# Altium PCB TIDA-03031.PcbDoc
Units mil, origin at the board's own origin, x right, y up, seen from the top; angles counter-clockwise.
Board outline 3300 x 2000 mil, 2 copper layers (Top Layer, Bottom Layer), stack 61.2 mil thick; 63 components, 29 nets, 150 pads, 94 vias.
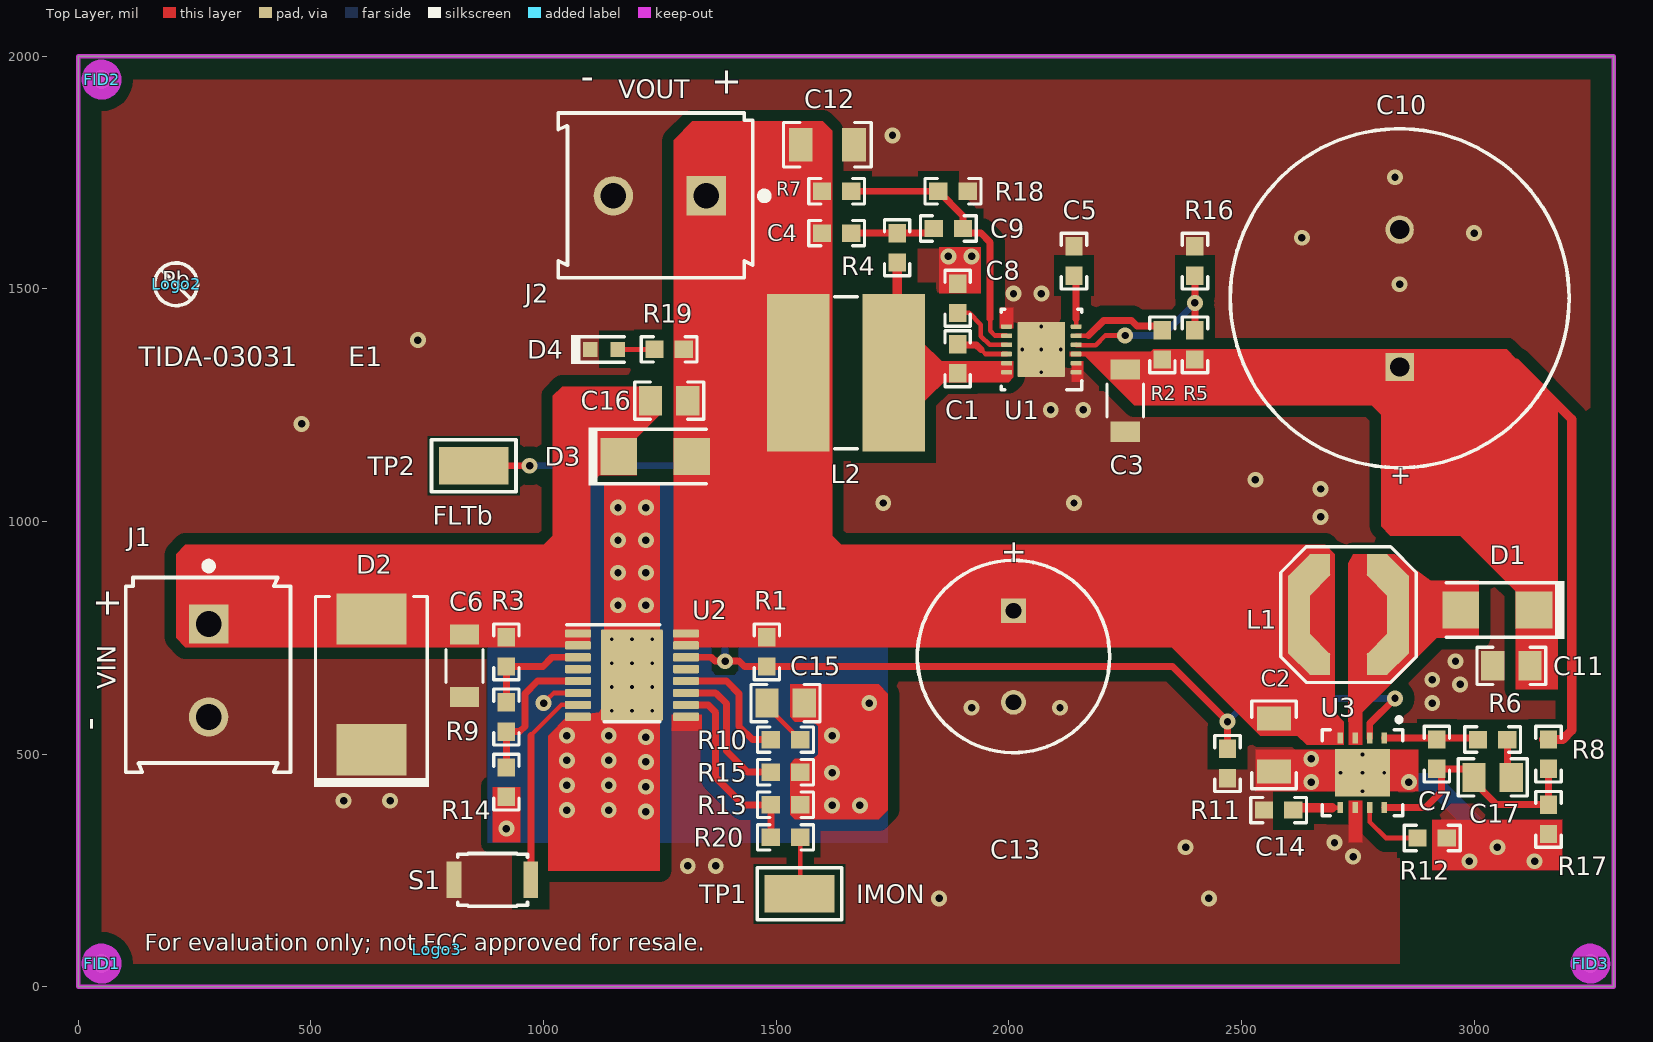
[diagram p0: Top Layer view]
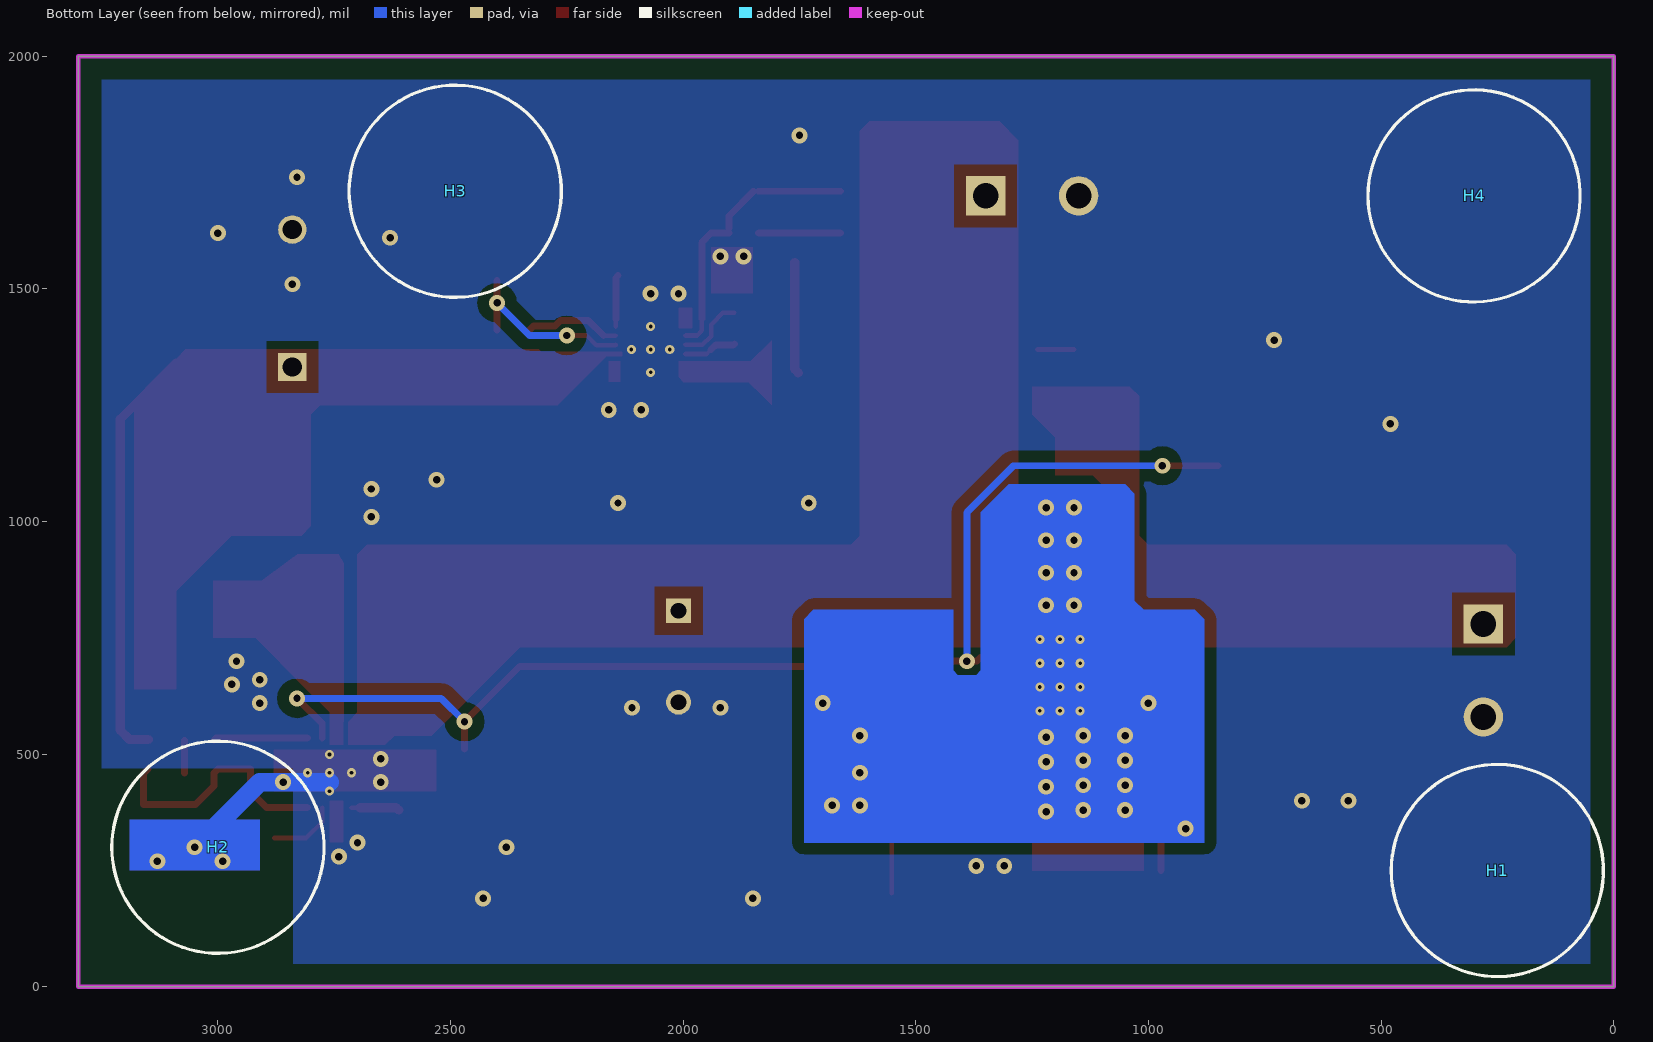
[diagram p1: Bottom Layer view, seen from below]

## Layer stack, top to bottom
Top Solder: solder mask 0.4, Solder Resist, Dk 3.5
Top Layer: signal copper 2.8
Dielectric1: core 55.6, FR-4, Dk 4.8
Bottom Layer: signal copper 2.8
Bottom Solder: solder mask 0.4, Solder Resist, Dk 3.5

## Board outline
0,0 0,2000 3300,2000 3300,0

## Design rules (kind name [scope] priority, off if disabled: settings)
AcuteAngle [All] p1: minimum=4.50000000000000E+0001 checktracksonly=FALSE
AssemblyTestPointUsage [All] p1: valid=2
BoardOutlineClearance BoardOutlineClearance_MountingHoles [OnCopper and InComponentClass('Mounting Holes')] p1: gap=40
BoardOutlineClearance BoardOutlineClearance_Poly [OnCopper and IsPoly] p2: gap=25
BoardOutlineClearance [OnCopper and Not InComponentClass('Logo') and not InComponentClass('FiducialMark') and not InRegion(1000,500,4000,800) and not InPoly] p3: gap=75
Clearance Clearance_Keepouts [((IsTrack Or IsArc) And Not InPoly) And IsFree and IsKeepOut vs ((IsTrack Or IsArc) And Not InPoly) And IsFree and IsKeepOut] p1: gap=0
Clearance Clearance_Poly [InPolygon] p2: gap=25
Clearance [All] p3: gap=7.87
ComponentClearance ComponentClearance_MountingHoles_FiducialMarks [InComponentClass('Mounting Holes') vs InComponentClass('FiducialMark')] p1: gap=50 collisioncheckmode=3 verticalgap=10 showdistances=FALSE
ComponentClearance ComponentClearance_Shunt [InComponentClass('Header') vs InComponentClass('Shunt')] p2: gap=0 collisioncheckmode=3 verticalgap=0 showdistances=FALSE
ComponentClearance ComponentClearance_Logo [InComponentClass('Logo')] p3: gap=50 collisioncheckmode=3 verticalgap=10 showdistances=FALSE
ComponentClearance ComponentClearance_ScrewToNut [(HasFootprint('NY PMS 440 0025 PH')) vs (HasFootprint('Keystone_1902C'))] p4: gap=5 collisioncheckmode=3 verticalgap=10 showdistances=FALSE
ComponentClearance ComponentClearance_MountingHoles [InComponentClass('Mounting Holes')] p5: gap=250 collisioncheckmode=3 verticalgap=100000 showdistances=FALSE
ComponentClearance ComponentClearance_SmallPassives [HasFootprint('0201*') or HasFootprint('0402*') or HasFootprint('0508') or HasFootprint('0603*') or HasFootprint('0612') or HasFootprint('0805*') or HasFootprint('0815*') or HasFootprint('0830*') or HasFootprint('1206*') or HasFootprint('1210*') or HasFootprint('1808*') or HasFootprint('1812*') or HasFootprint('1825*') or HasFootprint('2010*') or HasFootprint('2220*') or HasFootprint('2225*') or HasFootprint('2512*') or HasFootprint('2728*') or HasFootprint('3518*') vs HasFootprint('0201*') or HasFootprint('0402*') or HasFootprint('0508') or HasFootprint('0603*') or HasFootprint('0612') or HasFootprint('0805*') or HasFootprint('0815*') or HasFootprint('0830*') or HasFootprint('1206*') or HasFootprint('1210*') or HasFootprint('1808*') or HasFootprint('1812*') or HasFootprint('1825*') or HasFootprint('2010*') or HasFootprint('2220*') or HasFootprint('2225*') or HasFootprint('2512*') or HasFootprint('2728*') or HasFootprint('3518*')] p6: gap=14.96 collisioncheckmode=3 verticalgap=10 showdistances=FALSE
ComponentClearance ComponentClearance_THtoSMT [IsThruComponent vs IsSMTComponent] p7: gap=40 collisioncheckmode=3 verticalgap=30 showdistances=FALSE
ComponentClearance ComponentClearance_THtoTH [IsThruComponent vs IsThruComponent] p8: gap=30 collisioncheckmode=3 verticalgap=30 showdistances=FALSE
ComponentClearance [All] p9: gap=30 collisioncheckmode=3 verticalgap=10 showdistances=FALSE
DiffPairsRouting [All] p1: maxlimit=100 minlimit=10 mostfreqgap=10 toplayer_minwidth=15 toplayer_maxwidth=15 toplayer_prefwidth=15 bottomlayer_minwidth=15 bottomlayer_maxwidth=15 bottomlayer_prefwidth=15 maxuncoupledlength=1000
FabricationTestPointUsage TestPointUsage [All] p1: valid=2 allowmultiple=FALSE
FabricationTestpoint Testpoint [All] p1: side=3 testpointundercomponent=TRUE minsize=40 maxsize=100 preferedsize=60 minholesize=0 maxholesize=40 preferedholesize=32 testpointgrid=1 allowsidetop=TRUE allowsidebottom=TRUE usegrid=TRUE gridtolerance=0.01
FanoutControl Fanout_LCC [IsLCC] p1: bgadir=Out bgaviamode=Centered fanoutstyle=Auto fanoutdirection=Alternating viagrid=1 // Fanout_LCC (Default Rule)
FanoutControl Fanout_BGA [IsBGA] p2: bgadir=Out bgaviamode=Centered fanoutstyle=Auto fanoutdirection=Alternating viagrid=1 // Fanout_BGA (Default Rule)
FanoutControl Fanout_Default [All] p4: bgadir=Out bgaviamode=Centered fanoutstyle=Auto fanoutdirection=Alternating viagrid=1 // Fanout_Default (Default Rule)
FanoutControl Fanout_Small [(CompPinCount < 5)] p5: bgadir=Out bgaviamode=Centered fanoutstyle=Auto fanoutdirection=OutThenIn viagrid=1 // Fanout_Small (Default Rule)
Height [All] p1: minheight=0 maxheight=1100 prefheight=500
HoleSize [All] p1: absolutevalues=TRUE maxlimit=251 minlimit=7.87 maxpercent=80.000 minpercent=20.000
MinimumAnnularRing MinimumAnnularRing_ThermalPadVias [IsVia and InAnyComponent] p1: minimumring=5.91
MinimumAnnularRing [All] p2: minimumring=8
MinimumSolderMaskSliver MinimumSolderMaskSliver_Logo [InComponentClass('Logo') vs InComponentClass('Logo')] p1: minsoldermaskwidth=0.7
MinimumSolderMaskSliver [All] p2: minsoldermaskwidth=3.94
PlaneConnect [All] p1: planeconnectstyle=Direct reliefexpansion=10 reliefentries=4 reliefconductorwidth=10 reliefairgap=10
PolygonConnect [All] p1: connectstyle=Direct reliefconductorwidth=10 reliefentries=4 polygonreliefangle="90 Angle" airgapwidth=10
RoutingVias ThermalPadVias [IsVia and InAnyComponent] p1: holewidth=7.87 width=19.68 viastyle="Through Hole" minholewidth=7.87 minwidth=19.68 maxholewidth=12.99 maxwidth=23.62
RoutingVias [All] p2: holewidth=16 width=34 viastyle="Through Hole" minholewidth=7.87 minwidth=26 maxholewidth=40 maxwidth=65
SilkToBoardRegionClearance [Not ((IsComment or IsDesignator) And (Hide <> 'False')) and not InRegion(1000,500,4000,800)] p1:
SilkToSilkClearance SilkToSilkClearance_Pb-FreeLogo [(HasFootprint('Pb-Free_Overlay_Medium') OR HasFootprint('Pb-Free_Overlay_Small')) vs (HasFootprint('Pb-Free_Overlay_Medium') OR HasFootprint('Pb-Free_Overlay_Small'))] p1: silktosilkclearance=0
SilkToSilkClearance [All] p2: silktosilkclearance=4
SilkToSolderMaskClearance SilkToComponentPadClearance [IsPad and InAnycomponent] p1: minsilkscreentomaskgap=5 clearancetoexposedcopper=TRUE
SilkToSolderMaskClearance "Silk to Solder Mask Opening" [All] p2: minsilkscreentomaskgap=4 clearancetoexposedcopper=FALSE
SolderMaskExpansion [All] p1: expansion=1.97
Width [All] p1: maxlimit=100 minlimit=6 preferedwidth=10 checkconnectedcopper=TRUE
14 further rules are at their usual default settings.

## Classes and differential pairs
component class TIDA-03031: C1 C2 C3 C4 C5 C6 C7 C8 C9 C10 C11 C12 C13 C14 C15 C16 C17 D1 D2 D3 D4 J1 J2 L1 L2 R1 R2 R3 R4 R5 R6 R7 R8 R9 R10 R11 R12 R13 R14 R15 R16 R17 R18 R19 R20 S1 TP1 TP2 U1 U2 U3
component class TIDA-03031_Hardware: FID1 FID2 FID3 H1 H2 H3 H4 Logo2 Logo3 ZZ1 ZZ2 ZZ3
component class FiducialMark: FID1 FID2 FID3
component class AssemblyNote: ZZ1 ZZ2 ZZ3

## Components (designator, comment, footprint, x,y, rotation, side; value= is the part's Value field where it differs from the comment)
C1 "GRM188R72A103KA01D" 0603 1890,1350 r90 top
C2 "GRM31MR71H105KA88L" 1206 2570,520 r270 top
C3 "GRM31CR72A105KA01L" 1206_180 2250,1260 r270 top
C4 "GRM188R72A332KA01D" 0603 1630,1620 r0 top
C5 "GRM188R71C223KA01D" 0603 2140,1560 r90 top
C6 "GRM31CR72A105KA01L" 1206_180 830,690 r270 top
C7 "GRM1885C1H470JA01D" 0603 2920,500 r270 top
C8 "GRM188R71C105KA12D" 0603 1890,1480 r270 top
C9 "GRM188R72A104KA35D" 0603 1870,1630 r0 top
C10 "UHE1H122MHD6" HE_1800x2500 2840,1480 r90 top
C11 "GRM21BR72A104KAC4L" 0805_HV 3080,690 r0 top
C12 "GRM31MR71H105KA88L" 1206 1610,1810 r0 top
C13 "UHE1V221MPD6" UHE_1000x1250 2010,710 r270 top
C14 "GRM188R71C105KA12D" 0603 2580,380 r180 top
C15 "GRM219R71C225KE15" 0805_HV 1520,610 r0 top
C16 "GRM21BR72A104KAC4L" 0805_HV 1270,1260 r180 top
C17 "GRM219R71C104KA01D" 0805_HV 3040,450 r0 top
D1 "B160-13-F" SMA 3050,810 r180 top
D2 "SMCJ28CA" SMC 630,650 r90 top
D3 "SMAJ51CA" SMA 1240,1140 r0 top
D4 "LTST-C190GKT" LED_LTST-C190 1130,1370 r180 top
FID1 "Fiducial" Fiducial10-20 50,50 r0 top
FID2 "Fiducial" Fiducial10-20 50,1950 r0 top
FID3 "Fiducial" Fiducial10-20 3250,50 r0 top
H1 "SJ-5303 (CLEAR)" Bumpon_SJ5003Transparent 250,250 r180 bottom
H2 "SJ-5303 (CLEAR)" Bumpon_SJ5003Transparent 3000,300 r180 bottom
H3 "SJ-5303 (CLEAR)" Bumpon_SJ5003Transparent 2490,1710 r180 bottom
H4 "SJ-5303 (CLEAR)" Bumpon_SJ5003Transparent 300,1700 r180 bottom
J1 "VIN" TEC_282841-2 280,680 r270 top
J2 "VOUT" TEC_282841-2 1250,1700 r180 top
L1 "LPS6235-333MLB" LPS6235 2730,800 r0 top
L2 "LPS8045B-333MRB" LPS8045B 1650,1320 r180 top
Logo2 "Pb-Free Symbol" Pb-Free_Overlay_Small 210,1510 r0 top
Logo3 "FCC disclaimer" FCC_disclaimer 770,80 r0 top
R1 "CRCW0603100KFKEA" 0603 1480,720 r90 top
R2 "CRCW0603511KFKEA" 0603 2330,1380 r90 top
R3 "CRCW0603715KFKEA" 0603 920,720 r90 top
R4 "CRCW0603100KFKEA" 0603 1760,1588.5 r270 top
R5 "CRCW0603165KFKEA" 0603 2400,1380 r270 top
R6 "CRCW0603715KFKEA" 0603 3040,531.5 r0 top
R7 "CRCW0603226KFKEA" 0603 1630,1710 r180 top
R8 "CRCW060343K2FKEA" 0603 3160,500 r90 top
R9 "CRCW060320K0FKEA" 0603 920,580 r90 top
R10 "CRCW060310K0FKEA" 0603 1520,531.32 r180 top
R11 "CRCW060340K2FKEA" 0603 2470,480 r90 top
R12 "CRCW060343K2FKEA" 0603 2910,320 r180 top
R13 "CRCW060320K0FKEA" 0603 1520,391.32 r180 top
R14 "CRCW060330K1FKEA" 0603 920,440 r90 top
R15 "CRCW06036K04FKEA" 0603 1520,461.32 r180 top
R16 "CRCW060310K0FKEA" 0603 2400,1560 r270 top
R17 "CRCW06031K15FKEA" 0603 3160,360 r90 top
R18 "CRCW060330K1FKEA" 0603 1880,1710 r180 top
R19 "CRCW060320K0FKEA" 0603 1270,1370 r0 top
R20 "CRCW0603100KFKEA" 0603 1520,321.32 r0 top
S1 "SKRKAEE010" SW_SKRKAEE010 890,230 r0 top
TP1 "IMON" Keystone_5019 1550,200 r180 top
TP2 "FLTb" Keystone_5019 850,1120 r0 top
U1 "LM5160DNTR" DNT0012B 2070,1370 r180 top
U2 "TPS26600PWPR" PWP0016D_N 1190,670 r0 top
U3 "LM5002SD/NOPB" SDC08A 2760,460 r270 top
ZZ1 "These assemblies are ESD sensitive, ESD precautions shall be observed." AssemblyNote 185,3829.11 r0 top
ZZ2 "These assemblies must be clean and free from flux and all contaminants. Use of no clean flux is not acceptable." AssemblyNote 185,3740.56 r0 top
ZZ3 "These assemblies must comply with workmanship standards IPC-A-610 Class 2, unless otherwise specified." AssemblyNote 185,3652 r0 top

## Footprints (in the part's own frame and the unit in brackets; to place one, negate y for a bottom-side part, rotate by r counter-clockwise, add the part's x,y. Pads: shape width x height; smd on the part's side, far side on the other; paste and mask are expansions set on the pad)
0603 [mm] "0603 from SM-752 data"
  rect 1x0.95 smd: 1(-0.8,0) 2(0.8,0)
  silkscreen extent -1.52,-0.69 1.52,0.69, body extent -0.87,-0.47 0.87,0.47, height 1
0805_HV [mil] "0805 with 30mil clearance between pads"
  rect 50x63 smd: 1(-40,0) 2(40,0)
  silkscreen extent -74,-40 74,40, body extent -43,-29 43,29, height 57
1206 [mm] "1206 from SM-752 data"
  rect 1.3x1.85 smd: 1(-1.45,0) 2(1.45,0)
  silkscreen extent -2.4,-1.21 2.4,1.21, body extent -1.7,-0.9 1.7,0.9, height 1.35
1206_180 [mm] "1206_180"
  rect 1.1x1.6 smd: 1(-1.7,0) 2(1.7,0)
  silkscreen extent -0.9,-1 0.9,1, body extent -1.75,-0.95 1.75,0.95, height 1.8
AssemblyNote [mil] "Assembly Note"
Bumpon_SJ5003Transparent [mil] "3M Hemispherical Bumpon transparent"
  round 1 on Mech4: 0(0,0)
  silkscreen extent -228,-228 228,228, body extent -219,-218 219,218, height 197
DNT0012B [mm] "SON, 12-Leads, Body 4x4mm, Pitch 0.5mm"
  rrect40% 0.6x0.25 smd: 1(-1.9,1.25) 2(-1.9,0.75) 3(-1.9,0.25) 4(-1.9,-0.25) 5(-1.9,-0.75) 6(-1.9,-1.25) 7(1.9,-1.25) 8(1.9,-0.75) 9(1.9,-0.25) 10(1.9,0.25) 11(1.9,0.75) 12(1.9,1.25)
  rrect4% 2.6x3 smd paste-1.3: 13(0,0)
  silkscreen extent -2.2,-2.2 2.2,2.2, body extent -2,-2 2,2, height 0.81
FCC_disclaimer [mil]
Fiducial10-20 [mm]
  round 1 smd mask+0.5: 1(0,0)
  Top Layer keep-out circle w1.178: c0,0 r0.5
HE_1800x2500 [mm] "TH, 2-Leads, Dia 18mm, Pin Spacing 7.5mm"
  rect 1.55x1.55 hole 1.05: 1(-3.75,0)
  round 1.55 hole 1.05: 2(3.75,0)
  silkscreen extent -9.25,-9.25 9.25,9.25, body extent -9.25,-9.25 9.26,9.25, height 27.01
Keystone_5019 [mm] "Test Point, Miniature, SMT"
  rect 3.8x2.03 smd: 1(0,0)
  silkscreen extent -2.31,-1.42 2.31,1.42, body extent -1.9,-1.02 1.9,1.02, height 2.29
LED_LTST-C190 [mm] "Lite-On"
  rect 0.8x0.8 smd: 1(-0.75,0) 2(0.75,0)
  silkscreen extent -1.1,-0.8 1.8,0.8, body extent -0.85,-0.45 0.85,0.45, height 0.9
LPS6235 [mm] "Coilcraft recommended land pattern.  Document 587-2, rev 10/17/08"
  rect 1.2x4.25 smd: 1(-2.7,0) 2(2.7,0)
  rect 1.68x1.6 smd rot 135: 1(-2.126,-2.151) 2(2.126,2.151)
  rect 1.68x1.6 smd rot 45: 1(-2.126,2.151) 2(2.126,-2.151)
  rect 1.125x1.2 smd: 1(-1.562,-2.7) 1(-1.562,2.7) 2(1.562,-2.7) 2(1.562,2.7)
  silkscreen extent -3.7,-3.7 3.7,3.7, body extent -3.1,-3.1 3.1,3.1, height 3.52
LPS8045B [mm] "COILCRAFT"
  rect 3.4x8.61 smd: 1(-2.605,0) 2(2.605,0)
  silkscreen extent -0.6,-4.15 0.6,4.15, body extent -4.04,-4.04 4.04,4.04, height 4.7
Pb-Free_Overlay_Small [mil]
  silkscreen extent -46,-46 46,46
PWP0016D_N [mm] "TSOP, 16-Leads, Body 5x4.4mm, Pitch 0.65mm, Exposed Pad, IPC Medium Density"
  rrect22% 1.4x0.45 smd: 1(-2.95,2.275) 2(-2.95,1.625) 3(-2.95,0.975) 4(-2.95,0.325) 5(-2.95,-0.325) 6(-2.95,-0.975) 7(-2.95,-1.625) 8(-2.95,-2.275) 9(2.95,-2.275) 10(2.95,-1.625) 11(2.95,-0.975) 12(2.95,-0.325) 13(2.95,0.325) 14(2.95,0.975) 15(2.95,1.625) 16(2.95,2.275)
  rrect6% 3.4x5 smd paste-2 mask-2: 17(0,0)
  rrect4% 2.48x3.4 on Top Solder: 17(0,0)
  rrect4% 2.48x3.4 on Top Paste: 17(0,0)
  silkscreen extent -3.55,-2.55 1.5,2.75, body extent -3.21,-2.5 3.21,2.5, height 1
SDC08A [mm] "SON, 8-Leads, Body 4x4mm, Pitch 0.8mm, NSC Recommended"
  rect 0.6x0.3 smd paste-0.15 mask+0.051: 1(-1.9,1.2) 2(-1.9,0.4) 3(-1.9,-0.4) 4(-1.9,-1.2) 5(1.9,-1.2) 6(1.9,-0.4) 7(1.9,0.4) 8(1.9,1.2)
  rect 2.6x3 smd paste-1.5 mask+0.051: 9(0,0)
  silkscreen extent -3.02,-2.2 2.35,2.2, body extent -2.05,-2.05 2.05,2.05, height 0.8
SMA [mm] "Molded Diode, 2-Leads, Body 4.3x2.6mm, IPC Medium Density, based on OnSemi component dimensions and land pattern"
  rect 2x2 smd: 1(-2,0) 2(2,0)
  silkscreen extent -3.66,-1.57 2.79,1.57, body extent -2.6,-1.3 2.6,1.3, height 2.42
SMC [mil] "Molded Diode, 2-Leads, Body 6.9x5.8mm, IPC Medium Density, based on OnSemi component dimensions and land patterns"
  rect 110x150 smd: 1(-140.49,0) 2(140.49,0)
  silkscreen extent -221,-124 189,123, body extent -156,-116 156,116, height 91
SW_SKRKAEE010 [mm] "Alps recommended land pattern"
  rect 0.8x2 smd: 1(-2.1,0) 2(2.1,0)
  silkscreen extent -1.9,-1.44 1.92,1.44, body extent -2.4,-1.45 2.4,1.45, height 1.96
TEC_282841-2 [mm] "TE Connectivity"
  rect 2.15x2.15 hole 1.4: 1(-2.54,0)
  round 2.15 hole 1.4: 2(2.54,0)
  silkscreen extent -5.9,-4.52 5.55,4.47, body extent -5.08,-4.52 5.58,4.48, height 15.2
UHE_1000x1250 [mm] "TH, 2-Leads, Dia 10mm, Pin Spacing 5mm"
  rect 1.35x1.35 hole 0.85: 1(-2.5,0)
  round 1.35 hole 0.85: 2(2.5,0)
  silkscreen extent -5.25,-5.25 5.25,5.25, body extent -5.25,-5.25 5.26,5.25, height 14.01

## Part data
C1: "CAP, CERM, 0.01 µF, 100 V, +/- 10%, X7R, 0603"
C2 C12: "CAP, CERM, 1 µF, 50 V, +/- 10%, X7R, 1206"
C3 C6: "CAP, CERM, 1 µF, 100 V, +/- 10%, X7R, 1206"
C4: "CAP, CERM, 3300 pF, 100 V, +/- 10%, X7R, 0603"
C5: "CAP, CERM, 0.022 µF, 16 V, +/- 10%, X7R, 0603"
C7: "CAP, CERM, 47 pF, 50 V, +/- 5%, C0G/NP0, 0603"
C8 C14: "CAP, CERM, 1 µF, 16 V, +/- 10%, X7R, 0603"
C9: "CAP, CERM, 0.1 µF, 100 V, +/- 10%, X7R, 0603"
C10: "CAP, AL, 1200 µF, 50 V, +/- 20%, TH"
C11 C16: "CAP, CERM, 0.1 µF, 100 V, +/- 10%, X7R, 0805"
C13: "CAP, AL, 220 µF, 35 V, +/- 20%, TH"
C15: "CAP, CERM, 2.2 µF, 16 V, +/- 10%, X7R, 0805"
C17: "CAP, CERM, 0.1 µF, 16 V, +/- 10%, X7R, 0805"
D1: "Diode, Schottky, 60 V, 1 A, SMA"
D2: "Diode, TVS, Bi, 28 V, 45.4 Vc, SMC"
D3: "Diode, TVS, Bi, 51 V, 400 W, SMA"
D4: "LED, Green, SMD"
FID1 FID2 FID3: "Fiducial mark.  There is nothing to buy or mount."
H1 H2 H3 H4: "Bumpon, Hemisphere, 0.44 X 0.20, Clear"
J1 J2: library part 282841-2, "Terminal Block, 2x1, 5.08mm, TH"
L1: "Inductor, Shielded Drum Core, Ferrite, 33 µH, 1.3 A, 0.18 ohm, SMD"
L2: "Inductor, Shielded, Ferrite, 33 µH, 1.2 A, 0.121 ohm, SMD"
Logo2: library part Pb-Free
Logo3: library part FCC_disclaimer, "FCC_disclaimer"
R1 R4 R20: "RES, 100 k, 1%, 0.1 W, 0603"
R2: "RES, 511 k, 1%, 0.1 W, 0603"
R3 R6: "RES, 715 k, 1%, 0.1 W, 0603"
R5: "RES, 165 k, 1%, 0.1 W, 0603"
R7: "RES, 226 k, 1%, 0.1 W, 0603"
R8 R12: "RES, 43.2 k, 1%, 0.1 W, 0603"
R9 R13 R19: "RES, 20.0 k, 1%, 0.1 W, 0603"
R10 R16: "RES, 10.0 k, 1%, 0.1 W, 0603"
R11: "RES, 40.2 k, 1%, 0.1 W, 0603"
R14 R18: "RES, 30.1 k, 1%, 0.1 W, 0603"
R15: "RES, 6.04 k, 1%, 0.1 W, 0603"
R17: "RES, 1.15 k, 1%, 0.1 W, 0603"
S1: "Switch, Push Button, SMD"
TP1 TP2: library part 5019, "Test Point, Miniature, SMT"
U1: "Wide Input 65V, 1.5A Synchronous Step-Down DC-DC Converter, DNT0012B"
U2: "4.5V-55V, 0.15A-2A, 150mOhm Industrial eFuse, PWP0016D"
U3: "High Voltage Switch Mode Regulator, 8-pin LLP, Pb-Free"
ZZ1 ZZ2 ZZ3: library part AssemblyNote

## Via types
v1: diameter 34, hole 16, Top Layer to Bottom Layer, 72 vias
v2: diameter 19.68, hole 7.87, Top Layer to Bottom Layer, 16 vias
v3: diameter 19.68, hole 7.87, Top Layer to Bottom Layer, tented both sides, 6 vias

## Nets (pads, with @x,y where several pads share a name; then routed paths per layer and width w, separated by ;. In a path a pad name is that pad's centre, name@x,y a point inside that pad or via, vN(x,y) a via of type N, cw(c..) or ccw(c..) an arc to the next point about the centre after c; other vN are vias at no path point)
GND: C2.2 C3.2 C5.2 C6.2 C8.1 C10.2 C11.1 C12.2 C13.2 C14.2 D2.1 D4.2 J1.2 J2.2 R11.1 R12.1 R16.1 R17.1 R18.1 S1.1 U1.1 U1.2 U1.7 U1.13 U2.9 U3.6 U3.9 | length 348
  Bottom Layer w40: 2760,440 2910,440 v1(3050,300)
  other v1: 1850,190 2430,190 1310,260 1370,260 2990,270 3130,270 2740,280 2380,300 2700,310 570,400 670,400 2650,440 2860,440 2650,490 1920,600 2110,600 2910,610 2970,650 2910,660 2960,700 2670,1010 1730,1040 2140,1040 2670,1070 2530,1090 480,1210 2090,1240 2160,1240 730,1390 2010,1490 2070,1490 2840,1510 1870,1570 1920,1570 2630,1610 3000,1620 2830,1740 1750,1830
  other v2: 2760,420.63 2712.76,460 2760,460 2807.24,460 2760,499.37 2070,1320.79 2028.66,1370 2070,1370 2111.34,1370 2070,1419.21
NetC1_1: C1.1 L2.1 R4.2 U1.11 U1.12 | length 240.1
  Top Layer w20: L2.1 1760,1327.44 R4.2
NetC1_2: C1.2 U1.10 | length 114
  Top Layer w10: 1940,1370 1949.84,1360.16 U1.10
  Top Layer w15: C1.2 1891.5,1380 1930,1380 1940,1370
NetC3_1: C3.1 C10.1 C11.2 D1.1 R2.1 R5.2 R8.2 U1.3 | length 906.5
  Top Layer w20: 3090,1340 3210,1220 3210,551.5 3190,531.5 R8.2@3150,531.5
NetC4_2: C4.2 C9.1 R4.1 | length 177
  Top Layer w15: C4.2 C9.1@1838.5,1620
NetC5_1: C5.1 U1.6 | length 111.3
  Top Layer w10: U1.6 2144.8,1435.2
  Top Layer w15: C5.1 2144.8,1523.7 2144.8,1435.2
NetC7_1: C7.1 R6.1 U3.1 | length 203.2
  Top Layer w15: U3.1 3003.7,534.8 R6.1@3008.5,530
NetC7_2: C7.2 C17.1 R8.1 R17.2 U3.8 | length 545.4
  Top Layer w15: U3.8 2895.2,385.2 2930,420 2930,468.5 3000,468.5 3008.5,460 3008.5,431.5 3048.5,391.5 R17.2 3160,458.5 R8.1@3150,468.5
NetC8_2: C8.2 U1.9 | length 148
  Top Layer w10: C8.2 1914.76,1448.5 1940,1423.27 1940,1398.81 1958.97,1379.84 U1.9
NetC9_2: C9.2 R7.1 R18.2 U1.8 | length 575.3
  Top Layer w10: 1960,1435.97 1960,1410 1970,1400 1994.72,1400 U1.8
  Top Layer w15: R7.1 R18.2@1838.5,1710 ; R18.2 1901.5,1657.01 C9.2 ; C9.2@1901.5,1620 1940,1620 1960,1600 1960,1435.97
NetC14_1: C14.1 U3.5 | length 103.4
  Top Layer w10: 2694.8,385.2 U3.5
  Top Layer w20: C14.1 2616.69,385.2 2694.8,385.2
NetC15_1: C15.1 R10.1 | length 108.3
  Top Layer w10: C15.1 1480,602.82 R10.1
NetC17_2: C17.2 R6.2 | length 70
  Top Layer w15: C17.2@3071.5,460 R6.2@3071.5,530
NetD1_2: D1.2 L1.2 U3.3
NetD4_1: D4.1 R19.1 | length 79
  Top Layer w10: D4.1 R19.1
NetR1_1: R1.1 R11.2 TP2.1 U2.14 U3.2 | length 2669.5
  Top Layer w15: TP2.1 v1(970,1120) ; U2.14 1360,708.39 1368.39,700 v1(1390,700) 1420,700 1431.5,688.5 R1.1 2351.5,688.5 v1(2470,570) R11.2 ; U3.2 2775.75,565.75 v1(2830,620)
  Bottom Layer w15: v1(970,1120) 1290,1120 1390,1020 v1(1390,700) ; v1(2470,570) 2520,620 v1(2830,620)
NetR2_2: R2.2 U1.5 | length 207.5
  Top Layer w10: U1.5 2171.1,1399.53
  Top Layer w15: 2171.1,1399.53 2203.94,1432.37 2263.41,1432.37 2275.83,1419.95 2321.54,1419.95 R2.2
NetR3_1: R3.1 R9.2 U2.3 | length 239.1
  Top Layer w15: R9.2 R3.1 998.5,688.5 1018.39,708.39 U2.3
NetR5_1: R5.1 R16.2 U1.4 | length 400.5
  Top Layer w10: U1.4 2144.8,1379.15 2186.79,1379.15 2207.64,1400 v1(2250,1400)
  Top Layer w15: R5.1 v1(2400,1470) R16.2@2400,1518.5
  Bottom Layer w15: v1(2250,1400) 2330,1400 v1(2400,1470)
NetR9_1: R9.1 R14.2 U2.5 | length 316.9
  Top Layer w15: R14.2 R9.1 948.5,548.5 960,560 960,630 987.2,657.2 U2.5
NetR10_2: R10.2 U2.12 | length 275.5
  Top Layer w15: U2.12 1392.8,657.2 1420,630 1420,560 1448.68,531.32 R10.2
NetR12_2: R12.2 U3.7 | length 147.9
  Top Layer w10: U3.7 2775.75,354.25 2810,320 R12.2
NetR13_2: R13.2 R20.1 U2.10 | length 423.3
  Top Layer w15: U2.10 1353.98,606.02 1370,590 1370,450 1428.68,391.32 R13.2 R20.1
NetR15_2: R15.2 U2.11 | length 312.4
  Top Layer w15: U2.11 1370,631.61 1392.87,608.74 1392.87,507.13 1438.68,461.32 R15.2
NetR20_2: R20.2 TP1.1 | length 121.9
  Top Layer w10: R20.2@1550,319.82 R20.2 TP1.1@1551.5,201.5
NetS1_2: S1.2 U2.7 | length 418.7
  Top Layer w10: 972.68,540.24 1038.46,606.02 U2.7
  Top Layer w15: S1.2@972.68,250 972.68,540.24
RTN: C15.2 R13.1 R14.1 R15.1 U2.6 U2.8 U2.17@1190,670 | length 68.7
  Top Layer w10: v1@1010,620 1021.61,631.61 U2.6
  other v1: 920,340 1220,376.67 1050,380 1140,380 1620,390 1680,390 1220,430 1050,433.33 1140,433.33 1620,460 1220,483.33 1050,486.67 1140,486.67 1220,536.67 1050,540 1140,540 1620,540 1000,610 1700,610 1160,820 1220,820 1160,890 1220,890 1160,960 1220,960 1160,1030 1220,1030
  other v2: 1146.69,644.41 1190,644.41 1233.31,644.41 1146.69,695.59 1190,695.59 1233.31,695.59
  other v3: 1146.69,593.23 1190,593.23 1233.31,593.23 1146.69,746.77 1190,746.77 1233.31,746.77
VIN: C6.1 C16.2 D2.2 D3.1 J1.1 R3.2 U2.1 U2.2
VOUT: C2.1 C4.1 C12.1 C13.1 C16.1 D3.2 J2.1 L1.1 L2.2 R1.2 R7.2 R19.2 U2.15 U2.16 U3.4
pads on no net: FID1.1 FID2.1 FID3.1 H1.0 H2.0 H3.0 H4.0 U2.4 U2.13 U2.17@1190,670

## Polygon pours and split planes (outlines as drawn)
GND on Bottom Layer "BOTTOM_LAYER_GND_P006" (solid, remove dead copper, pour order 6): 50,1950 3250,1950 3250,470 2838.15,470 2838.15,50 50,50
GND on Top Layer "TOP_LAYER_GND_P004" (solid, remove dead copper, pour order 4): 50,50 2840,50 2840,360 3250,360 3250,1950 50,1950

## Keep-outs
Keep-Out Layer:
  the board outline again, w10
  text ".Layer_Name" at 577,-858.49 h60

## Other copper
Top Layer:
  rectangle net GND: 1850,1490 1940,1590
  rectangle net GND: 2530,420 2880,510
  rectangle net GND: 2910,250 3190,360
  rectangle net RTN: 890,310 950,430
  rectangle net NetD1_2: 2730,520 2760,580
  rectangle net NetC3_1: 2130,1355 2320,1366
  rectangle net NetC1_1: 1850,1310 2010,1345
  rectangle net GND: 1275,550 1340,585
  rectangle net GND: 2730,310 2760,400
  rectangle net GND: 2135,1300 2160,1345
  rectangle net GND: 1980,1415 2010,1460
  pour cut-out: 1630,1590 1640,1580 1640,1130 1680,1130 1680,1570 1690,1580 1680,1590
  region net VOUT: 1280,730 2040,730 2350,730 2540,540 2620,540 2640,520 2720,520 2720,570 2700,590 2700,930 2680,950 2040,950 1640,950 1620,970 1620,1840 1600,1860 1480,1860 1320,1860 1280,1820
  region net VIN: 1100,730 230,730 210,750 210,930 230,950 1000,950 1020,970 1020,1270 1040,1290 1250,1290 1250,1230 1200,1180 1200,1100 1120,1100 1100,1080 1100,950 1100,790
  region net NetD1_2: 2730,910 2740.25,930.25 2830,930.25 2907,873 3010,873 3010,750.25 2920.25,750.25 2810,640 2760,590 2760,570 2730,570 2730,600
  region net NetC3_1: 3180,870 3180,1050 3180,1260 3090,1350 3070,1370 2310,1370 2300,1360 2160,1360 2190,1330 2270,1250 2780,1250 2800,1230 2800,1200 2800,990 2820,970 2970,970 3090,850 3090,640 3180,640
  region net NetC1_1: 2010,1340 2010,1310 2000,1300 1860,1300 1830,1270 1810,1250 1810,1390 1860,1340
  region net RTN: 1250,250 1010,250 1010,540 1050,580 1120,590 1130,610 1130,1080 1250,1080
  region net RTN: 1530,650 1530,580 1540,570 1580,570 1590,560 1590,500 1580,490 1540,490 1530,480 1530,370 1540,360 1720,360 1740,380 1740,630 1720,650
  text ".Layer_Name" at 577,-858.49 h60
Bottom Layer:
  region net GND: 3190,360 2910,360 2910,250 3190,250
  region net RTN: 880,310 880,790 900,810 1010,810 1030,830 1030,1060 1050,1080 1300,1080 1360,1020 1360,810 1360,690 1360,680 1370,670 1410,670 1420,680 1420,690 1420,730 1420,810 1720,810 1740,790 1740,310
  text ".Layer_Name" at 577,-858.49 h60

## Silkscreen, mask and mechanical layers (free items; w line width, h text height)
Top Overlay:
  text "-" at 1080,1910 h100
  text "+" at 1360,1900 h100
  text "TIDA-03031      E1" at 130,1320 h72.83
  text "+" at 30,780 h100
  text "-" at 70,550 h100 r90
  text ".Layer_Name" at 577,-858.49 h60
Bottom Overlay:
  text ".Layer_Name" at 577,-858.49 h60
Top Paste:
  text ".Layer_Name" at 577,-858.49 h60
Bottom Paste:
  text ".Layer_Name" at 577,-858.49 h60
Top Solder:
  text ".Layer_Name" at 577,-858.49 h60
  text ".Layer_Name" at 577,-858.49 h60
Bottom Solder:
  text ".Layer_Name" at 577,-858.49 h60
Drill Guide:
  text ".Layer_Name" at 577,-858.49 h60
M1 Board Outline:
  the board outline again, w10
  text ".Layer_Name" at 577,-858.49 h60
M2 Board Dimensions:
  rectangle: 0,-275 125,-150
  rectangle: 125,-400 500,-275
  lines w7: 0,-275 1000,-275 ; 125,-400 125,-150 ; 250,-400 250,-150 ; 500,-400 500,-150 ; 750,-400 750,-150 ; 0,-400 1000,-400 1000,-150 0,-150 0,-400
  text ".Layer_Name" at 577,-858.49 h60
M3 3D STEP Top:
  text ".Layer_Name" at 577,-858.49 h60
M4 3D STEP Bottom:
  text ".Layer_Name" at 577,-858.49 h60
M5 Assembly Top:
  lines w10: -292,-930.17 6308,-930.17 ; -292,-726.83 6310,-726.83 ; -292,-523.5 -292,-1133.5 3713,-1133.5 6310,-1133.5 6310,-523.5 -291.5,-523.5 -291.5,-1133.5 1284,-1133.5 ; 2173,-1133.5 2173,-523.5 ; 3440,-726.83 3440,-523.5 ; 4280,-726.83 4280,-523.5 ; 4902,-1140 4902,-937.17
  text "COMPONENTS MARKED 'DNP' SHOULD NOT BE POPULATED." at 1153.5,-318.5 h60
  text "ASSEMBLY VARIANT:" at 1153,-434 h60
  text ".VariantName" at 2189,-434 h60
  text "PCB VIEWED FROM TOP SIDE" at -228.5,-655.67 h60
  text "BOARD #:" at 2248,-655.67 h60
  text ".PRJ_Number" at 2793.5,-655.67 h60
  text "REV:" at 3638,-655.67 h60
  text ".PCB_Rev" at 3929.5,-655.67 h60
  text "SVN REV:" at 4476,-655.67 h60
  text ".VersionControl_RevNumber" at 4982,-655.67 h60
  text "TID #:" at 2248,-859 h60
  text ".TID" at 2793.5,-859 h60
  text "PLOT NAME =" at -228.5,-1064.34 h60
  text ".plot_File_Name" at 577,-1064.34 h60
  text "GENERATED    :" at 2250,-1064.34 h60
  text ".Print_Date" at 3119.5,-1064.34 h60
  text ".Print_Time" at 3848.5,-1064.34 h60
  text "TEXAS INSTRUMENTS" at 5113,-1064.34 h60
M6 Assembly Bottom:
  lines w10: -292.5,-727.33 6309.5,-727.33 ; -290.5,-930.67 6309.5,-930.67 ; 1115.5,-1140.5 1115.5,-937.67 ; 1737.5,-727.33 1737.5,-524 ; 2577.5,-727.33 2577.5,-524 ; 3844.5,-1134 3844.5,-524 ; 4733.5,-1134 6309,-1134 6309,-524 -292.5,-524 -292.5,-1134 2304.5,-1134 6309.5,-1134 6309.5,-524
  text "COMPONENTS MARKED 'DNP' SHOULD NOT BE POPULATED." at 6102,-318 h60
  text ".VariantName" at 5058,-434 h60
  text "ASSEMBLY VARIANT:" at 6097,-434 h60
  text ".VersionControl_RevNumber" at 1035.5,-656.17 h60
  text "SVN REV:" at 1541.5,-656.17 h60
  text ".PCB_Rev" at 2088,-656.17 h60
  text "REV:" at 2379.5,-656.17 h60
  text ".PRJ_Number" at 3224,-656.17 h60
  text "BOARD #:" at 3769.5,-656.17 h60
  text "PCB VIEWED FROM BOTTOM SIDE" at 6246,-656.17 h60
  text ".TID" at 3224,-859.5 h60
  text "TID #:" at 3769.5,-859.5 h60
  text "TEXAS INSTRUMENTS" at 904.5,-1064.84 h60
  text ".Print_Time" at 2169,-1064.84 h60
  text ".Print_Date" at 2898,-1064.84 h60
  text "GENERATED    :" at 3767.5,-1064.84 h60
  text ".plot_File_Name" at 5440.5,-1064.84 h60
  text "PLOT NAME =" at 6246,-1064.84 h60
M9 Title Sheet:
  drawing of 57 lines, arcs and shapes, not listed
  text "1" at 739.84,8036.5 h70
  text "2" at 3235.5,8036.5 h70
  text "3" at 5724.84,8036.5 h70
  text "4" at 8231.51,8036.5 h70
  text "5" at 10730.5,8036.5 h70
  text "6" at 13235.5,8036.5 h70
  text "A" at -416.5,6893.5 h70
  text "A" at 14383.5,6893.5 h70
  text "B" at -416.5,4513.5 h70
  text "B" at 14383.5,4513.5 h70
  text "C" at -416.5,2138.5 h70
  text "C" at 14383.5,2138.5 h70
  text "PROJECT TITLE:" at 11343.5,277.5 h45
  text ".PRJ_Title" at 11393.5,144.17 h70
  text "DESIGNED FOR:" at 11343.5,-23.5 h45
  text ".PRJ_Customer" at 11393.5,-163.5 h70
  text "D" at -416.5,-231.5 h70
  text "D" at 14383.5,-231.5 h70
  text "FILE NAME:" at 11343.5,-323.5 h45
  text ".PCB_File_Name_No_Path" at 11393.5,-443.5 h70
  text "Texas Instruments (TI) and/or its licensors do not warrant the accuracy or completeness of this specification" at 6374,-605.34 h45
  text "ENGINEER:" at 11343.5,-613.5 h45
  text "LAYOUT BY:" at 12848.5,-613.5 h45
  text "or any information contained therein. TI and/or its licensors do not warrant that this design will meet" at 6329.01,-718 h45
  text ".PRJ_Engineer" at 11393.5,-768.49 h70
  text ".PCB_Layout" at 12899,-768.49 h70
  text "the specifications, will be suitable for your application or fit for any particular purpose, or will operate in" at 6329.01,-830.67 h45
  text ".Layer_Name" at 577,-858.49 h60
  text "ALTIUM DESIGNER VERSION:" at 12848.5,-923.5 h45
  text "an implementation. TI and/or its licensors do not warrant that the design is production worthy. You should" at 6329.01,-943.33 h45
  text "completely validate and test your design implementation to confirm the system functionality for your application." at 6374,-1056 h45
  text ".print_Scale" at 11393.5,-1056.83 h70
  text ".Application_BuildNumber" at 12899,-1056.83 h70
  text "1" at 739.84,-1263.5 h70
  text "2" at 3235.5,-1263.5 h70
  text "3" at 5724.84,-1263.5 h70
  text "4" at 8231.51,-1263.5 h70
  text "5" at 10730.5,-1263.5 h70
  text "6" at 13235.5,-1263.5 h70
M10 Fab Notes:
  drawing of 173 lines, arcs and shapes, not listed
  text "DESIGN INFORMATION" at 12378.02,6201 h60
  text "MIN. TRACK WIDTH:" at 11733.46,6021 h60
  text "8" at 12829.7,6021 h60
  text "MIL" at 12984.46,6021 h60
  text "MIN. CLEARANCE:" at 11733.46,5889 h60
  text "0.2" at 12769.7,5889 h60
  text "mm" at 12984.46,5889 h60
  text "MIN. VIA PAD SIZE:" at 11733.46,5757 h60
  text "24" at 12799.71,5757 h60
  text "MIL" at 12984.46,5757 h60
  text "0.05mm (2MIL)" at 12428.46,5615.29 h60
  text "MINIMUM ANNULAR RING" at 11404.23,5611 h60
  text "EXTERNAL" at 13136.46,5611 h60
  text "PER" at 11604.23,5493 h60
  text "IPC-D-275 CLASS 2 LEVEL C" at 11824.23,5493 h60
  text "MIL, HOLES" at 13312.46,5380.71 h60
  text "+/-" at 12920,5380 h60
  text "+/-" at 13774,5380 h60
  text "REGISTRATION TOLERANCES:" at 11404.23,5375 h60
  text "METAL" at 12604,5375 h60
  text "5" at 13180.2,5375 h60
  text "3" at 14013.2,5375 h60
  text "MIL" at 14129.46,5375 h60
  text "+/-" at 13774,5262 h60
  text "HOLE SIZE TOLERANCE (UNLESS OTHERWISE SPECIFIED):" at 11404.23,5257 h60
  text "3" at 14013.2,5257 h60
  text "MIL" at 14129.46,5257 h60
  text "MATERIAL:" at 11329.46,5047.54 h60
  text "FR-4 High Tg" at 12315.9,4907.21 h60
  text "FR-408" at 11750.46,4898.64 h60
  text "OTHER" at 13238.46,4898.64 h60
  text "X" at 12161,4895 h60
  text "62 MIL (1.6mm) +/-10%" at 12070.56,4735.92 h60
  text "THICKNESS:" at 11404.23,4731.64 h60
  text "X" at 11942.4,4731.64 h60
  text "OTHER" at 13355.46,4731.64 h60
  text "TOLERANCE:" at 11404.23,4573.64 h60
  text "X" at 12243.53,4573.64 h60
  text "ANSI IPC-6012 TYPE 3 CLASS 2" at 12430.48,4573.64 h60
  text "OTHER +/-" at 12430.46,4417.64 h60
  text "BOW & TWIST:" at 11404.23,4260.64 h60
  text "X" at 12243.53,4260.64 h60
  text "ANSI IPC-6012 TYPE 3 CLASS 2" at 12430.48,4260.64 h60
  text "OTHER +/-" at 12430.46,4102.13 h60
  text "DRILLING:" at 11329.46,3963.64 h60
  text "REFERENCE:" at 11404.23,3846.64 h60
  text "X" at 12052.46,3846.64 h60
  text "AS SHOWN" at 12239.46,3846.64 h60
  text "X" at 12953.46,3846.64 h60
  text "NC_DRILL FILES" at 13090.46,3846.64 h60
  text "PTH COPPER THICKNESS:" at 11404.23,3688.64 h60
  text "X" at 12534.46,3688.64 h60
  text "20-30 um" at 12671.46,3688.64 h60
  text "OTHER" at 13388.46,3688.64 h60
  text "BOARD FINISH:" at 11329.46,3529.64 h60
  text "SILKSCREEN:" at 11484.68,3411.64 h60
  text "X" at 12433.46,3411.64 h60
  text "TOP" at 12559.46,3411.64 h60
  text "BOTTOM" at 13070.46,3411.64 h60
  text "SILKSCREEN COLOR:" at 11484.68,3244.64 h60
  text "X" at 12432.42,3244.64 h60
  text "WHITE" at 12559.46,3244.64 h60
  text "OTHER" at 13070.46,3244.64 h60
  text "X" at 12563.42,3085.44 h60
  text "GREEN" at 12690.46,3085.44 h60
  text "OTHER" at 13308.46,3085.44 h60
  text "SOLDER RESIST COLOR:" at 11484.68,3074.64 h60
  text "X" at 12563.42,2915.44 h60
  text "MATTE" at 12690.46,2915.44 h60
  text "SEMI-GLOSS" at 13308,2914.8 h60
  text "IMMERSION GOLD (ENIG)" at 12390.46,2726.92 h60
  text "ENEPIG" at 13728,2723.64 h60
  text "SURFACE FINISH:" at 11329.46,2722.64 h60
  text "X" at 12203.51,2722.64 h60
  text "IMM. TIN/SILVER OR EQUIV" at 11659,2565.64 h60
  text "OTHER" at 13090.46,2565.64 h60
  text "ARRAY/PANEL:" at 11329.46,2386.64 h60
  text "CUT AND TRIM PER M1 BOARD OUTLINE" at 12390.46,2382.35 h60
  text "N.C. ROUTE" at 12390.46,2230.64 h60
  text "X" at 13069.46,2230.64 h60
  text "V. SCORE" at 13256.46,2230.64 h60
  text "CERTIFICATION:" at 11329.46,2093.64 h60
  text "MATERIALS AND WORKMANSHIP FOR ALL PCBS" at 12054.46,2093.64 h60
  text "TO MEET OR EXCEED THE REQUIREMENTS OF:" at 12054.46,1995.64 h60
  text "X" at 11680.96,1859.13 h60
  text "ANSI IPC-A-600F CLASS ->" at 11819.96,1859.13 h60
  text "X" at 13459.02,1859.13 h60
  text "2" at 13577.96,1859.14 h60
  text "1" at 13262.96,1857.64 h60
  text "3" at 13931.96,1857.64 h60
  text "X" at 12495.02,1699.64 h60
  text "RoHS" at 12631.96,1699.64 h60
  text "OTHER" at 13276.36,1699.64 h60
  text "PER ORDER" at 13673.42,1699.64 h60
  text "ALL BOARDS MUST MEET OR EXCEED UL94-V0 REQUIREMENTS." at 11357,1534 h60
  text "PCB MUST BEAR THE UL94V-0 UL REGISTERED MATERIAL ID NUMBER" at 11357,1414 h60
  text "ADDITIONAL REQUIREMENTS:" at 11329.46,1240.64 h60
  text "MICROSECTION:" at 11404.23,1125.64 h60
  text "YES" at 12309.96,1125.64 h60
  text "REQUIRED" at 13171.46,969.49 h60
  text "BARE BOARD ELEC. TEST:" at 11404.23,966.64 h60
  text "NONE" at 12709.96,966.64 h60
  text "X" at 13044.46,966.64 h60
  text "PER ORDER" at 13763.46,966.64 h60
  text ".Layer_Name" at 577,-858.49 h60
M11 Gerber Information:
  lines w10: -292,-930.17 6308,-930.17 ; -292,-726.83 6310,-726.83 ; -292,-523.5 -292,-1133.5 3713,-1133.5 6310,-1133.5 6310,-523.5 -291.5,-523.5 -291.5,-1133.5 1284,-1133.5 ; 2173,-1133.5 2173,-523.5 ; 3440,-726.83 3440,-523.5 ; 4280,-726.83 4280,-523.5 ; 4902,-1140 4902,-937.17
  text "ALL ARTWORK VIEWED FROM TOP SIDE" at -228.5,-655.67 h60
  text "BOARD #:" at 2248,-655.67 h60
  text ".PRJ_Number" at 2793.5,-655.67 h60
  text "REV:" at 3638,-655.67 h60
  text ".PCB_Rev" at 3929.5,-655.67 h60
  text "SVN REV:" at 4476,-655.67 h60
  text ".VersionControl_RevNumber" at 4982,-655.67 h60
  text "LAYER NAME =" at -228.5,-858.49 h60
  text "TID #:" at 2248,-859 h60
  text ".TID" at 2793.5,-859 h60
  text "PLOT NAME =" at -228.5,-1064.34 h60
  text ".plot_File_Name" at 577,-1064.34 h60
  text "GENERATED    :" at 2250,-1064.34 h60
  text ".Print_Date" at 3119.5,-1064.34 h60
  text ".Print_Time" at 3848.5,-1064.34 h60
  text "TEXAS INSTRUMENTS" at 5113,-1064.34 h60
M12 Stackup:
  drawing of 191 lines, arcs and shapes, not listed
  text "Layer" at 9727.5,7707.5 h60
  text "Name" at 10137.41,7707.5 h60
  text "Material" at 11067.16,7707.5 h60
  text "Thickness" at 11926.92,7707.5 h60
  text "Constant" at 12576.76,7707.5 h60
  text "Board Layer Stack" at 13146.62,7707.5 h60
  text "1" at 9727.5,7587.5 h60
  text "Top Overlay" at 10137.41,7587.5 h60
  text "2" at 9727.5,7467.5 h60
  text "Top Solder" at 10137.41,7467.5 h60
  text "Solder Resist" at 11067.16,7467.5 h60
  text "0.40mil" at 11926.92,7467.5 h60
  text "3.5" at 12576.76,7467.5 h60
  text "3" at 9727.5,7347.5 h60
  text "Top Layer" at 10137.41,7347.5 h60
  text "Copper" at 11067.16,7347.5 h60
  text "2.80mil" at 11926.92,7347.5 h60
  text "4" at 9727.5,7227.5 h60
  text "Dielectric1" at 10137.41,7227.5 h60
  text "FR-4" at 11067.16,7227.5 h60
  text "55.60mil" at 11926.92,7227.5 h60
  text "4.8" at 12576.76,7227.5 h60
  text "5" at 9727.5,7107.5 h60
  text "Bottom Layer" at 10137.41,7107.5 h60
  text "Copper" at 11067.16,7107.5 h60
  text "2.80mil" at 11926.92,7107.5 h60
  text "6" at 9727.5,6987.5 h60
  text "Bottom Solder" at 10137.41,6987.5 h60
  text "Solder Resist" at 11067.16,6987.5 h60
  text "0.40mil" at 11926.92,6987.5 h60
  text "3.5" at 12576.76,6987.5 h60
  text "7" at 9727.5,6867.5 h60
  text "Bottom Overlay" at 10137.41,6867.5 h60
  text ".Layer_Name" at 577,-858.49 h60
M13 Component Bodies Top:
  text ".Layer_Name" at 577,-858.49 h60
M14 Component Bodies Bottom:
  text ".Layer_Name" at 577,-858.49 h60
M15 Courtyards Top:
  text ".Layer_Name" at 577,-858.49 h60
M16 Courtyards Bottom:
  text ".Layer_Name" at 577,-858.49 h60
Drill Drawing:
  circle w10: c5363.8,3141.62 r27.66
  lines w10: 5336.14,2740.59 5391.46,2740.59 5391.46,2795.9 5336.14,2795.9 5336.14,2740.59 ; 5336.14,2878.87 5349.97,2878.87 5363.8,2865.04 5377.63,2878.87 5391.46,2878.87 5377.63,2892.7 5391.46,2906.53 5377.63,2906.53 5363.8,2920.36 5349.97,2906.53 5336.14,2906.53 5349.97,2892.7 5336.14,2878.87 ; 5336.14,3044.82 5391.46,3044.82 5363.8,2989.5 5336.14,3044.82 ; 5336.14,3238.42 5363.8,3252.25 5391.46,3238.42 5377.63,3266.08 5391.46,3293.74 5363.8,3279.91 5336.14,3293.74 5349.97,3266.08 5336.14,3238.42
  lines w12: 5286,2703.25 8518.76,2703.25 ; 5286,3325.54 8518.76,3325.54 ; 5624.17,2578.79 5624.17,3450 ; 5956.28,2578.79 5956.28,3450 ; 6593.29,2578.79 6593.29,3450 ; 6852.64,2578.79 6852.64,3450 ; 7228.06,2578.79 7228.06,3450 ; 7951.91,2578.79 7951.91,3450 ; 5286,2578.79 8518.76,2578.79 8518.76,3450 5286,3450 5286,2578.79
  text "Symbol" at 5360.68,3362.88 h72
  text "Quantity" at 5661.51,3362.88 h72
  text "Finished Hole Size" at 5993.62,3362.88 h72
  text "Plated" at 6630.62,3362.88 h72
  text "Hole Type" at 6889.98,3362.88 h72
  text "Drill Layer Pair" at 7265.4,3362.88 h72
  text "Hole Tolerance" at 7989.25,3362.88 h72
  text "22" at 5661.51,3238.42 h60
  text "7.87mil (0.200mm)" at 5993.62,3238.42 h60
  text "PTH" at 6630.62,3238.42 h60
  text "Round" at 6889.98,3238.42 h60
  text "Top Layer - Bottom Layer" at 7265.4,3238.42 h60
  text "72" at 5661.51,3113.96 h60
  text "16.00mil (0.406mm)" at 5993.62,3113.96 h60
  text "PTH" at 6630.62,3113.96 h60
  text "Round" at 6889.98,3113.96 h60
  text "Top Layer - Bottom Layer" at 7265.4,3113.96 h60
  text "2" at 5661.51,2989.5 h60
  text "33.46mil (0.850mm)" at 5993.62,2989.5 h60
  text "PTH" at 6630.62,2989.5 h60
  text "Round" at 6889.98,2989.5 h60
  text "Top Layer - Bottom Layer" at 7265.4,2989.5 h60
  text "2" at 5661.51,2865.04 h60
  text "41.34mil (1.050mm)" at 5993.62,2865.04 h60
  text "PTH" at 6630.62,2865.04 h60
  text "Round" at 6889.98,2865.04 h60
  text "Top Layer - Bottom Layer" at 7265.4,2865.04 h60
  text "4" at 5661.51,2740.59 h60
  text "55.12mil (1.400mm)" at 5993.62,2740.59 h60
  text "PTH" at 6630.62,2740.59 h60
  text "Round" at 6889.98,2740.59 h60
  text "Top Layer - Bottom Layer" at 7265.4,2740.59 h60
  text "102 Total" at 5661.51,2616.13 h60
  text ".Layer_Name" at 577,-858.49 h60
M17 Embedded Cavity:
  text ".Layer_Name" at 577,-858.49 h60
M18 Embedded Assembly:
  text ".Layer_Name" at 577,-858.49 h60
M19 Embedded Keepout:
  text ".Layer_Name" at 577,-858.49 h60

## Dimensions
0,-400 to 1000,-400 on M2 Board Dimensions
0,2000 to 3300,0 on M2 Board Dimensions
3300,0 to 0,2000 on M2 Board Dimensions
